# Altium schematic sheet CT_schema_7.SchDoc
size 287 x 160 mm
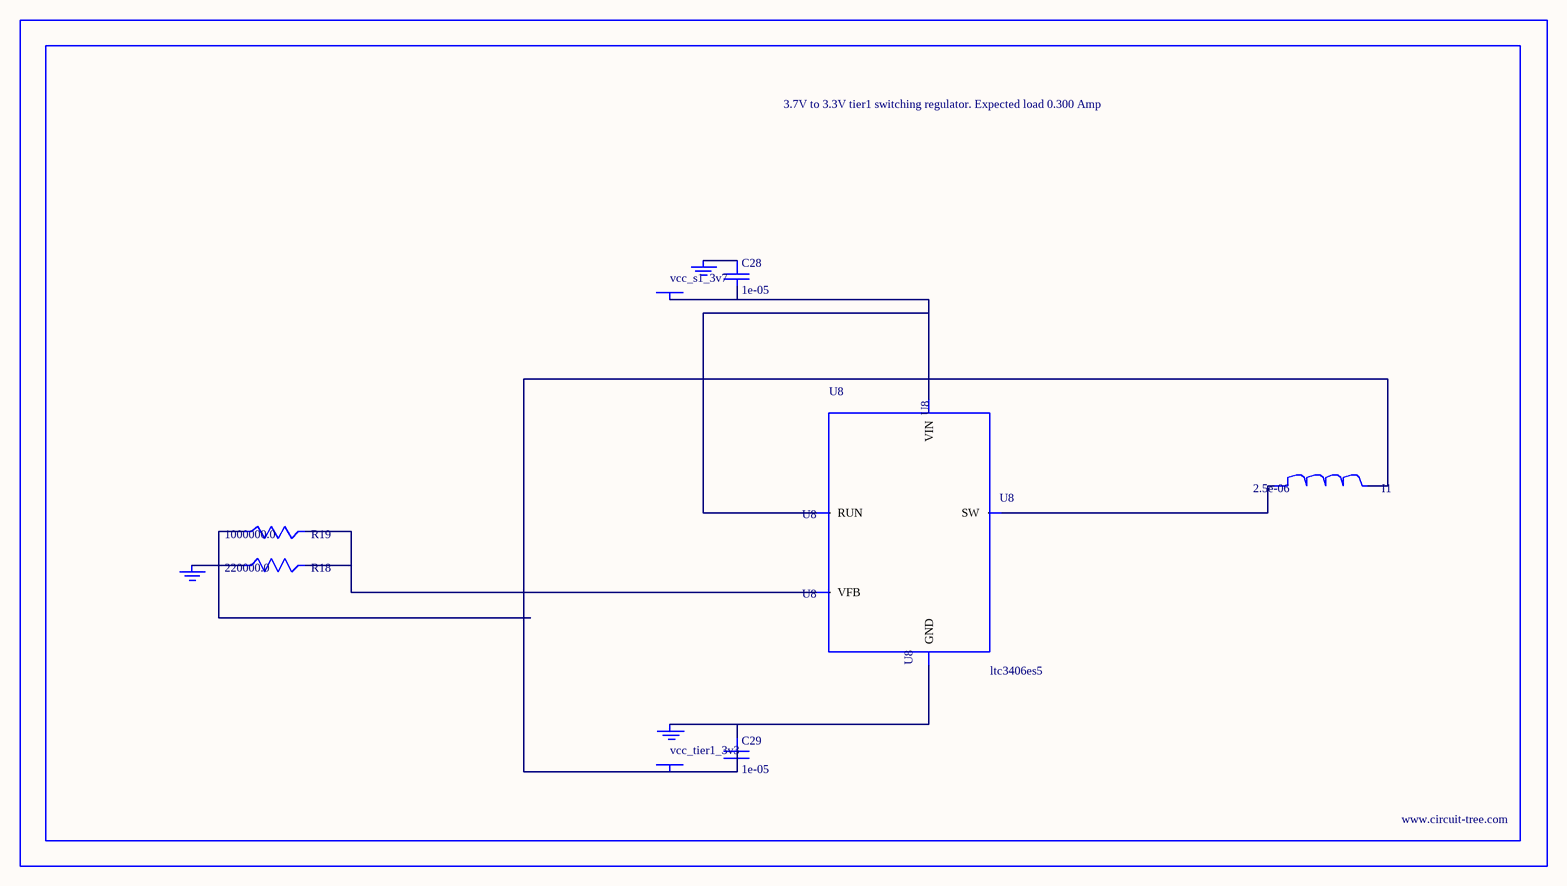
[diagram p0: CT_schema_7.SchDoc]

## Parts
BORDER6  (no value)
C28  1e-05  [C0805]
C29  1e-05  [C0805]
GND_INSTANCE_6_0  (no value)
GND_INSTANCE_6_1  (no value)
GND_INSTANCE_6_2  (no value)
I1  2.5e-06  [DR1040]
POWER_INSTANCE_6_0  vcc_tier1_3v3
POWER_INSTANCE_6_1  vcc_s1_3v7
R18  220000.0  [R0603]
R19  1000000.0  [R0603]
U8  ltc3406es5  [TSOT-23-5]

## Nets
NetC28_1: C28.1 GND_INSTANCE_6_1.0(GND)
NetC28_2: C28.2 POWER_INSTANCE_6_1.0(PWR) U8.1(RUN) U8.4(VIN)
NetC29_1: C29.1 GND_INSTANCE_6_0.0(GND) U8.2(GND)
NetC29_2: C29.2 I1.2 POWER_INSTANCE_6_0.0(PWR) R19.1
NetGND_INSTANCE_6_2_0: GND_INSTANCE_6_2.0(GND) R18.1
NetI1_1: I1.1 U8.3(SW)
NetR18_2: R18.2 R19.2 U8.5(VFB)

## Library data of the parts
BORDER6 = BORDER_PAGE6
C28 C29 = C0805C106K8RACTU
GND_INSTANCE_6_0-GND_INSTANCE_6_2 = GND
I1 = DR1040-2R5-R
POWER_INSTANCE_6_0 POWER_INSTANCE_6_1 = PWR
R18 = RC0603JR-07220KL
R19 = RC0603JR-071ML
